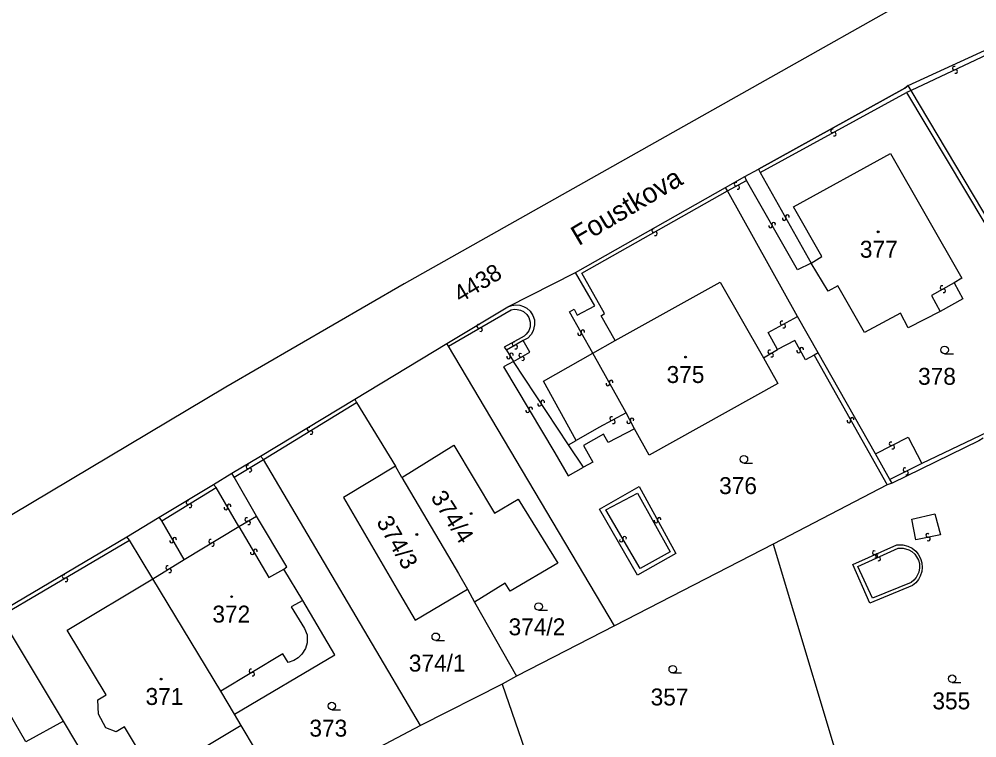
# Model space of a CAD drawing. Extents: x -600391 to -599491, y -1160176 to -1159402.
# Drawn here: x -600240 to -600143.9, y -1159597.8 to -1159525.7 of the extents above; entities that cross this region are included whole.
import ezdxf

# ---------------------------------------------------------------- set-up
doc = ezdxf.new("R2010")
doc.units = 0
for name, color, linetype in [('Level 1', 7, 'Continuous'), ('Level 11', 7, 'Continuous'), ('Level 13', 7, 'Continuous'), ('Level 3', 7, 'Continuous'), ('Level 4', 7, 'Continuous'), ('Level 5', 7, 'Continuous')]:
    doc.layers.add(name, color=color, linetype=linetype)

msp = doc.modelspace()

# ---------------------------------------------------------------- linework, layer by layer
at = {"layer": 'Level 1'}
for points in [[(-600107.73, -1159499.45), (-600113.87, -1159502.94), (-600201.37, -1159552.29), (-600219.23, -1159562.65), (-600266.03, -1159590.55), (-600270.37, -1159592.37), (-600271.85, -1159593.21), (-600272.01, -1159592.83), (-600281.12, -1159598.11), (-600280.42, -1159599.25), (-600280.87, -1159599.52), (-600276.57, -1159606.52), (-600297.82, -1159620.52), (-600312.66, -1159632.26), (-600336.82, -1159651.44), (-600337.7, -1159652.95), (-600337.93, -1159654.45), (-600337.54, -1159656.13), (-600336.82, -1159657.21), (-600349.22, -1159663.94), (-600350.24, -1159665.24), (-600350.91, -1159666.77), (-600351.08, -1159668.42)], [(-600318.84, -1159639.11), (-600306.21, -1159629.48), (-600295.86, -1159621.51), (-600283.38, -1159612.88), (-600275.25, -1159607.05), (-600263.73, -1159599.23), (-600256.89, -1159594.38), (-600242.07, -1159585.3), (-600229.19, -1159577.66), (-600225.93, -1159575.71), (-600220.47, -1159572.42), (-600218.63, -1159571.29), (-600215.77, -1159569.57), (-600206.32, -1159563.86), (-600197.09, -1159558.28), (-600190.96, -1159554.59), (-600184.16, -1159551.14), (-600169.13, -1159542.61), (-600167.2, -1159541.52), (-600165.81, -1159540.77), (-600151.14, -1159532.65), (-600150.81, -1159532.39), (-600141.91, -1159528.31)], [(-600150.81, -1159532.39), (-600141.91, -1159528.31)], [(-600150.81, -1159532.39), (-600151.14, -1159532.65), (-600165.81, -1159540.77)], [(-600150.52, -1159532.87), (-600150.81, -1159532.39)], [(-600132.7, -1159562.82), (-600150.52, -1159532.87)], [(-600160.52, -1159550.2), (-600159.45, -1159549.54), (-600162.31, -1159544.55), (-600152.57, -1159539.2), (-600145.42, -1159551.7), (-600146.18, -1159552.19)], [(-600167.2, -1159541.52), (-600165.81, -1159540.77)], [(-600169.13, -1159542.61), (-600167.2, -1159541.52)], [(-600184.16, -1159551.14), (-600169.13, -1159542.61)], [(-600168.94, -1159542.96), (-600169.13, -1159542.61)], [(-600161.9, -1159555.55), (-600168.94, -1159542.96)], [(-600147.6, -1159555.05), (-600150.8, -1159556.7), (-600151.56, -1159555.21), (-600155.19, -1159557.17), (-600157.86, -1159552.48), (-600158.83, -1159553.03), (-600160.52, -1159550.2)], [(-600190.96, -1159554.59), (-600184.16, -1159551.14)], [(-600180.2, -1159557.97), (-600169.65, -1159552.1), (-600165.3, -1159559.69)], [(-600146.18, -1159552.19), (-600145.32, -1159553.77), (-600147.6, -1159555.05)], [(-600197.09, -1159558.28), (-600190.96, -1159554.59)], [(-600159.82, -1159559.22), (-600161.9, -1159555.55)], [(-600182.43, -1159559.25), (-600180.2, -1159557.97)], [(-600206.32, -1159563.86), (-600197.09, -1159558.28)], [(-600196.92, -1159558.52), (-600197.09, -1159558.28)], [(-600180.26, -1159586.6), (-600196.92, -1159558.52)], [(-600184.1, -1159567.99), (-600187.39, -1159562.04), (-600182.43, -1159559.25)], [(-600165.3, -1159559.69), (-600163.87, -1159562.29), (-600176.8, -1159569.47), (-600178.24, -1159566.83)], [(-600154.08, -1159569.33), (-600159.82, -1159559.22)], [(-600215.77, -1159569.57), (-600206.32, -1159563.86)], [(-600206.32, -1159563.86), (-600206.14, -1159564.18)], [(-600206.14, -1159564.18), (-600202.24, -1159570.59)], [(-600178.24, -1159566.83), (-600180.91, -1159568.21), (-600181.37, -1159567.38), (-600183.36, -1159568.5), (-600182.43, -1159570.16), (-600183.38, -1159570.69)], [(-600143.28, -1159567.76), (-600143.71, -1159568.02), (-600152.42, -1159572.28)], [(-600201.6, -1159571.73), (-600196.36, -1159568.46), (-600192.29, -1159575.3), (-600189.93, -1159573.9), (-600185.96, -1159580.31), (-600190.71, -1159583.11), (-600191.23, -1159582.32), (-600194.3, -1159584.21)], [(-600184.87, -1159568.43), (-600184.1, -1159567.99)], [(-600183.38, -1159570.69), (-600184.87, -1159568.43)], [(-600218.63, -1159571.29), (-600215.77, -1159569.57)], [(-600215.46, -1159569.91), (-600215.77, -1159569.57)], [(-600152.65, -1159571.9), (-600154.08, -1159569.33)], [(-600199.71, -1159596.6), (-600215.46, -1159569.91)], [(-600202.24, -1159570.59), (-600207.44, -1159573.72), (-600201.82, -1159583.37), (-600200.24, -1159586.03), (-600195.02, -1159582.93)], [(-600201.6, -1159571.73), (-600202.24, -1159570.59)], [(-600220.47, -1159572.42), (-600218.63, -1159571.29)], [(-600218.4, -1159571.69), (-600218.63, -1159571.29)], [(-600225.93, -1159575.71), (-600220.47, -1159572.42)], [(-600216.17, -1159575.58), (-600218.4, -1159571.69)], [(-600201.6, -1159571.73), (-600196.57, -1159580.22), (-600195.91, -1159581.35), (-600195.02, -1159582.93)], [(-600152.92, -1159572.45), (-600164.35, -1159578.41)], [(-600152.42, -1159572.28), (-600152.92, -1159572.45)], [(-600152.42, -1159572.28), (-600152.65, -1159571.9)], [(-600229.19, -1159577.66), (-600225.93, -1159575.71)], [(-600213.44, -1159580.91), (-600213.14, -1159580.67), (-600216.17, -1159575.58)], [(-600242.07, -1159585.3), (-600229.19, -1159577.66)], [(-600228.92, -1159577.99), (-600229.19, -1159577.66)], [(-600226.56, -1159581.89), (-600228.92, -1159577.99)], [(-600164.35, -1159578.41), (-600180.26, -1159586.6)], [(-600164.35, -1159578.41), (-600148.22, -1159632.05)], [(-600211.53, -1159584.06), (-600213.44, -1159580.91)], [(-600217.72, -1159596.61), (-600221.38, -1159598.8), (-600220.1, -1159601.1), (-600225.09, -1159603.94), (-600229.42, -1159596.75), (-600230.25, -1159597.24), (-600231.28, -1159596.82), (-600232.01, -1159595.46), (-600232.08, -1159594.02), (-600231.24, -1159593.51), (-600235.15, -1159587.05), (-600226.56, -1159581.89)], [(-600219.75, -1159593.15), (-600226.56, -1159581.89)], [(-600195.02, -1159582.93), (-600194.3, -1159584.21)], [(-600218.37, -1159595.46), (-600208.32, -1159589.52), (-600211.53, -1159584.06)], [(-600194.3, -1159584.21), (-600190.1, -1159591.66)], [(-600235.53, -1159596.17), (-600241.83, -1159585.63)], [(-600180.26, -1159586.6), (-600190.1, -1159591.66)], [(-600190.1, -1159591.66), (-600191.54, -1159592.46)], [(-600191.54, -1159592.46), (-600199.71, -1159596.6)], [(-600191.54, -1159592.46), (-600174.95, -1159640.54)], [(-600235.53, -1159596.17), (-600239.31, -1159598.24), (-600242.26, -1159593.19), (-600245.05, -1159594.74), (-600245.74, -1159593.51), (-600251.18, -1159596.55), (-600250.59, -1159597.82), (-600255.47, -1159600.61), (-600255.02, -1159601.32)], [(-600218.37, -1159595.46), (-600219.75, -1159593.15)], [(-600217.72, -1159596.61), (-600218.37, -1159595.46)], [(-600231.72, -1159602.57), (-600235.53, -1159596.17)], [(-600213.4, -1159603.83), (-600217.72, -1159596.61)], [(-600199.71, -1159596.6), (-600213.4, -1159603.83)]]:
    msp.add_lwpolyline(points, dxfattribs=at)
at = {"layer": 'Level 13'}
for centre, start, end in [((-600146.187, -1159530.633), 62.30306, 294.89306), ((-600146.033, -1159530.968), 242.51752, 114.61552), ((-600158.397, -1159536.927), 66.01059, 298.10858), ((-600158.222, -1159537.252), 245.79613, 118.38613), ((-600168.066, -1159542.277), 65.81566, 297.91366), ((-600167.893, -1159542.602), 245.60121, 118.19121), ((-600163.241, -1159545.729), 156.49513, 29.08513), ((-600162.918, -1159545.551), 336.70958, 208.80758), ((-600164.621, -1159546.49), 157.11761, 29.21561), ((-600164.3, -1159546.309), 336.90316, 209.49316), ((-600176.339, -1159546.929), 66.85508, 298.95308), ((-600176.16, -1159547.251), 246.64063, 119.23063), ((-600147.409, -1159552.659), 66.19145, 298.78145), ((-600147.232, -1159552.982), 246.4059, 118.5039), ((-600163.467, -1159556.197), 65.91534, 298.01334), ((-600193.871, -1159556.549), 67.33331, 299.4313), ((-600193.689, -1159556.87), 247.11885, 119.70885), ((-600183.761, -1159557.269), 156.89409, 28.99209), ((-600183.439, -1159557.09), 336.67964, 209.26964), ((-600163.293, -1159556.522), 245.70088, 118.29088), ((-600190.35, -1159558.3), 66.7569, 299.3469), ((-600190.17, -1159558.621), 246.97136, 119.06936), ((-600164.692, -1159559.12), 67.73085, 299.82885), ((-600161.802, -1159559.018), 156.45215, 28.55015), ((-600161.479, -1159558.841), 336.2377, 208.8277), ((-600190.895, -1159559.609), 159.79178, 32.38178), ((-600190.584, -1159559.412), 340.00624, 212.10423), ((-600189.661, -1159559.459), 67.38517, 299.48317), ((-600189.479, -1159559.78), 247.17072, 119.76072), ((-600164.508, -1159559.439), 247.51639, 120.10639), ((-600180.599, -1159562.141), 336.31057, 208.90057), ((-600180.922, -1159562.318), 156.52503, 28.62303), ((-600188.978, -1159565.014), 158.04368, 30.63368), ((-600188.661, -1159564.827), 338.25814, 210.35613), ((-600187.775, -1159564.35), 160.79276, 32.89076), ((-600187.466, -1159564.149), 340.57831, 213.16831), ((-600180.547, -1159565.798), 65.70967, 298.29967), ((-600178.507, -1159565.934), 335.26769, 207.85769), ((-600156.418, -1159565.861), 336.75559, 208.85359), ((-600210.895, -1159566.882), 68.95622, 301.05422), ((-600180.373, -1159566.123), 245.92413, 118.02212), ((-600178.833, -1159566.105), 155.48215, 27.58015), ((-600156.741, -1159566.04), 156.54114, 29.13114), ((-600210.704, -1159567.197), 248.74176, 121.33176), ((-600152.522, -1159568.335), 64.35549, 296.45348), ((-600152.357, -1159568.664), 244.14103, 116.73103), ((-600217.024, -1159570.641), 68.56521, 300.66321), ((-600216.835, -1159570.958), 248.35076, 120.94076), ((-600151.131, -1159570.935), 63.65189, 296.24189), ((-600150.969, -1159571.266), 243.86634, 115.96434), ((-600223.045, -1159574.232), 68.87453, 300.97253), ((-600222.855, -1159574.547), 248.66008, 121.25008), ((-600218.921, -1159574.578), 337.46949, 210.05949), ((-600219.24, -1159574.762), 157.68395, 29.78194), ((-600217.152, -1159575.94), 67.80998, 299.90798), ((-600216.967, -1159576.259), 247.59552, 120.18552), ((-600176.102, -1159576.078), 155.90019, 28.49019), ((-600175.777, -1159575.903), 336.11465, 208.21264), ((-600148.846, -1159577.53), 48.82463, 281.41463), ((-600224.7, -1159578.092), 157.65678, 29.75478), ((-600224.381, -1159577.908), 337.44232, 210.03232), ((-600220.774, -1159578.111), 68.55166, 300.64965), ((-600220.585, -1159578.428), 248.3372, 120.9272), ((-600179.57, -1159578.002), 157.70182, 29.79982), ((-600179.251, -1159577.818), 337.48736, 210.07736), ((-600148.774, -1159577.891), 229.03909, 101.13709), ((-600216.589, -1159579.273), 157.64334, 30.23334), ((-600216.27, -1159579.088), 337.8578, 209.95579), ((-600154.214, -1159579.271), 61.44362, 293.54162), ((-600154.066, -1159579.608), 241.22917, 113.81917), ((-600153.914, -1159579.561), 61.57106, 293.66906), ((-600153.765, -1159579.898), 241.35661, 113.94661), ((-600225.086, -1159580.753), 69.26353, 301.36152), ((-600224.893, -1159581.067), 249.04907, 121.63907), ((-600235.472, -1159581.65), 67.98933, 300.08732), ((-600235.287, -1159581.969), 247.77487, 120.36487), ((-600216.734, -1159591.132), 68.10849, 300.69849), ((-600216.547, -1159591.449), 248.32294, 120.42094)]:
    msp.add_arc(centre, 0.184, start, end, dxfattribs=at)
at = {"layer": 'Level 3'}
for points in [[(-600141.7, -1159528.73), (-600150.52, -1159532.87)], [(-600165.64, -1159541.09), (-600150.99, -1159533.09)], [(-600150.52, -1159532.87), (-600150.99, -1159533.09)], [(-600150.99, -1159533.09), (-600133.33, -1159562.63), (-600149.44, -1159570.3)], [(-600165.81, -1159540.77), (-600165.64, -1159541.09)], [(-600167.02, -1159541.92), (-600167.2, -1159541.52)], [(-600165.64, -1159541.09), (-600160.52, -1159550.2)], [(-600168.94, -1159542.96), (-600167.02, -1159541.92)], [(-600160.52, -1159550.2), (-600161.9, -1159550.88), (-600167.02, -1159541.92)], [(-600180.2, -1159557.97), (-600181.61, -1159555.5), (-600181.28, -1159555.24), (-600183.55, -1159551.22), (-600168.94, -1159542.96)], [(-600182.43, -1159559.25), (-600184.78, -1159555.1), (-600184.32, -1159554.82), (-600183.99, -1159555.44), (-600182.23, -1159554.5), (-600184.16, -1159551.14)], [(-600146.18, -1159552.19), (-600148.45, -1159553.45), (-600147.6, -1159555.05)], [(-600196.92, -1159558.52), (-600190.64, -1159554.9), (-600190.31, -1159554.83), (-600190.01, -1159554.85), (-600189.68, -1159554.93), (-600189.39, -1159555.07), (-600189.07, -1159555.34), (-600188.86, -1159555.67), (-600188.71, -1159556.14), (-600188.73, -1159556.59), (-600188.86, -1159556.98), (-600189.11, -1159557.34), (-600189.31, -1159557.52), (-600189.62, -1159557.7), (-600191.33, -1159558.64), (-600191.11, -1159558.94)], [(-600190.96, -1159554.59), (-600190.55, -1159554.44), (-600190.16, -1159554.39), (-600189.77, -1159554.42), (-600189.38, -1159554.55), (-600189.07, -1159554.71), (-600188.73, -1159555.02), (-600188.44, -1159555.47), (-600188.29, -1159555.9), (-600188.27, -1159556.41), (-600188.41, -1159556.98), (-600188.62, -1159557.36), (-600188.96, -1159557.72), (-600189.42, -1159557.98)], [(-600163.9, -1159558.87), (-600164.86, -1159557.16), (-600161.9, -1159555.55)], [(-600189.42, -1159557.98), (-600191.11, -1159558.94)], [(-600190.38, -1159560.08), (-600188.77, -1159559.15), (-600189.42, -1159557.98)], [(-600160.24, -1159559.45), (-600161.1, -1159559.91), (-600162.19, -1159557.95), (-600163.9, -1159558.87)], [(-600191.11, -1159558.94), (-600190.38, -1159560.08)], [(-600165.3, -1159559.69), (-600163.9, -1159558.87)], [(-600190.38, -1159560.08), (-600191.4, -1159560.62), (-600186.25, -1159569.23), (-600184.9, -1159571.54), (-600183.38, -1159570.69)], [(-600184.87, -1159568.43), (-600190.38, -1159560.08)], [(-600179.1, -1159565.22), (-600182.43, -1159559.25)], [(-600159.82, -1159559.22), (-600160.24, -1159559.45)], [(-600160.24, -1159559.45), (-600152.92, -1159572.45)], [(-600215.46, -1159569.91), (-600206.14, -1159564.18)], [(-600179.1, -1159565.22), (-600181.82, -1159566.7), (-600184.1, -1159567.99)], [(-600178.24, -1159566.83), (-600179.1, -1159565.22)], [(-600154.08, -1159569.33), (-600150.8, -1159567.66), (-600149.44, -1159570.3)], [(-600218.4, -1159571.69), (-600215.46, -1159569.91)], [(-600149.44, -1159570.3), (-600152.65, -1159571.9)], [(-600220.22, -1159572.72), (-600220.47, -1159572.42)], [(-600225.67, -1159576.06), (-600220.22, -1159572.72)], [(-600217.94, -1159576.62), (-600220.22, -1159572.72)], [(-600177.96, -1159581.5), (-600181.75, -1159574.88), (-600177.78, -1159572.63), (-600174.1, -1159579.34), (-600177.96, -1159581.5)], [(-600177.69, -1159580.85), (-600181.13, -1159574.97), (-600177.96, -1159573.29), (-600174.69, -1159579.18), (-600177.69, -1159580.85)], [(-600150.04, -1159577.97), (-600150.44, -1159575.91), (-600148.14, -1159575.36), (-600147.57, -1159577.46), (-600150.04, -1159577.97)], [(-600225.67, -1159576.06), (-600225.93, -1159575.71)], [(-600223.41, -1159579.93), (-600225.67, -1159576.06)], [(-600217.94, -1159576.62), (-600216.17, -1159575.58)], [(-600223.41, -1159579.93), (-600217.94, -1159576.62)], [(-600217.94, -1159576.62), (-600214.92, -1159581.75), (-600213.44, -1159580.91)], [(-600241.83, -1159585.63), (-600228.92, -1159577.99)], [(-600154.66, -1159584.31), (-600156.34, -1159580.43), (-600151.93, -1159578.46), (-600151.35, -1159578.46), (-600150.84, -1159578.59), (-600150.41, -1159578.81), (-600150.05, -1159579.11), (-600149.79, -1159579.4), (-600149.56, -1159579.83), (-600149.43, -1159580.27), (-600149.39, -1159580.75), (-600149.43, -1159581.16), (-600149.59, -1159581.62), (-600149.77, -1159581.95), (-600150.05, -1159582.29), (-600150.37, -1159582.55), (-600154.66, -1159584.31)], [(-600154.4, -1159583.81), (-600155.86, -1159580.64), (-600151.81, -1159578.82), (-600151.32, -1159578.8), (-600150.75, -1159578.97), (-600150.43, -1159579.15), (-600150.15, -1159579.4), (-600149.96, -1159579.66), (-600149.78, -1159580), (-600149.68, -1159580.35), (-600149.66, -1159580.78), (-600149.73, -1159581.22), (-600150, -1159581.75), (-600150.25, -1159582.03), (-600150.51, -1159582.24), (-600154.4, -1159583.81)], [(-600226.56, -1159581.89), (-600223.41, -1159579.93)], [(-600211.53, -1159584.06), (-600212.68, -1159584.71), (-600211.34, -1159586.87), (-600211.09, -1159587.49), (-600211.09, -1159588.31), (-600211.26, -1159588.86), (-600211.62, -1159589.45), (-600211.99, -1159589.82), (-600212.41, -1159590.07), (-600213, -1159590.28), (-600213.53, -1159589.42), (-600219.75, -1159593.15)]]:
    msp.add_lwpolyline(points, dxfattribs=at)
at = {"layer": 'Level 5'}
for p, q in [((-600147.15, -1159559.29), (-600146.275, -1159559.29)), ((-600167.28, -1159570.26), (-600166.405, -1159570.26)), ((-600187.87, -1159585.04), (-600186.995, -1159585.04)), ((-600198.19, -1159588.07), (-600197.315, -1159588.07)), ((-600174.42, -1159591.33), (-600173.545, -1159591.33)), ((-600146.39, -1159592.28), (-600145.515, -1159592.28)), ((-600208.61, -1159595.02), (-600207.735, -1159595.02))]:
    msp.add_line(p, q, dxfattribs=at)
for centre, radius in [((-600153.82, -1159547.06), 0.09), ((-600153.82, -1159547.06), 0.0521), ((-600147.15, -1159558.915), 0.375), ((-600173.13, -1159559.63), 0.09), ((-600173.13, -1159559.63), 0.0521), ((-600167.28, -1159569.885), 0.375), ((-600194.65, -1159575.34), 0.09), ((-600194.65, -1159575.34), 0.0521), ((-600200.09, -1159577.43), 0.09), ((-600200.09, -1159577.43), 0.0521), ((-600218.66, -1159583.67), 0.09), ((-600218.66, -1159583.67), 0.0521), ((-600187.87, -1159584.665), 0.375), ((-600198.19, -1159587.695), 0.375), ((-600174.42, -1159590.955), 0.375), ((-600146.39, -1159591.905), 0.375), ((-600225.74, -1159591.94), 0.09), ((-600225.74, -1159591.94), 0.0521), ((-600208.61, -1159594.645), 0.375)]:
    msp.add_circle(centre, radius, dxfattribs=at)

# ---------------------------------------------------------------- texts
at = {"layer": 'Level 11'}
msp.add_text('Foustkova', height=2, rotation=30.72172, dxfattribs=at).set_placement((-600183.851, -1159548.511))
at = {"layer": 'Level 4'}
for s, p in [('377', (-600155.65, -1159549.66)), ('375', (-600175.037, -1159562.23)), ('378', (-600149.813, -1159562.41)), ('376', (-600169.766, -1159573.38)), ('372', (-600220.591, -1159586.27)), ('374/2', (-600190.885, -1159587.55)), ('374/1', (-600200.893, -1159591.19)), ('371', (-600227.298, -1159594.54)), ('357', (-600176.637, -1159594.59)), ('355', (-600148.374, -1159594.98)), ('373', (-600210.862, -1159597.72))]:
    msp.add_text(s, height=1.7, dxfattribs=at).set_placement(p)
for s, rotation, p in [('4438', 30.96378, (-600195.73, -1159554.22)), ('374/4', 302.2344, (-600198.758, -1159573.693)), ('374/3', 299.73609, (-600204.191, -1159576.157))]:
    msp.add_text(s, height=1.7, rotation=rotation, dxfattribs=at).set_placement(p)

doc.saveas('drawing.dxf')
